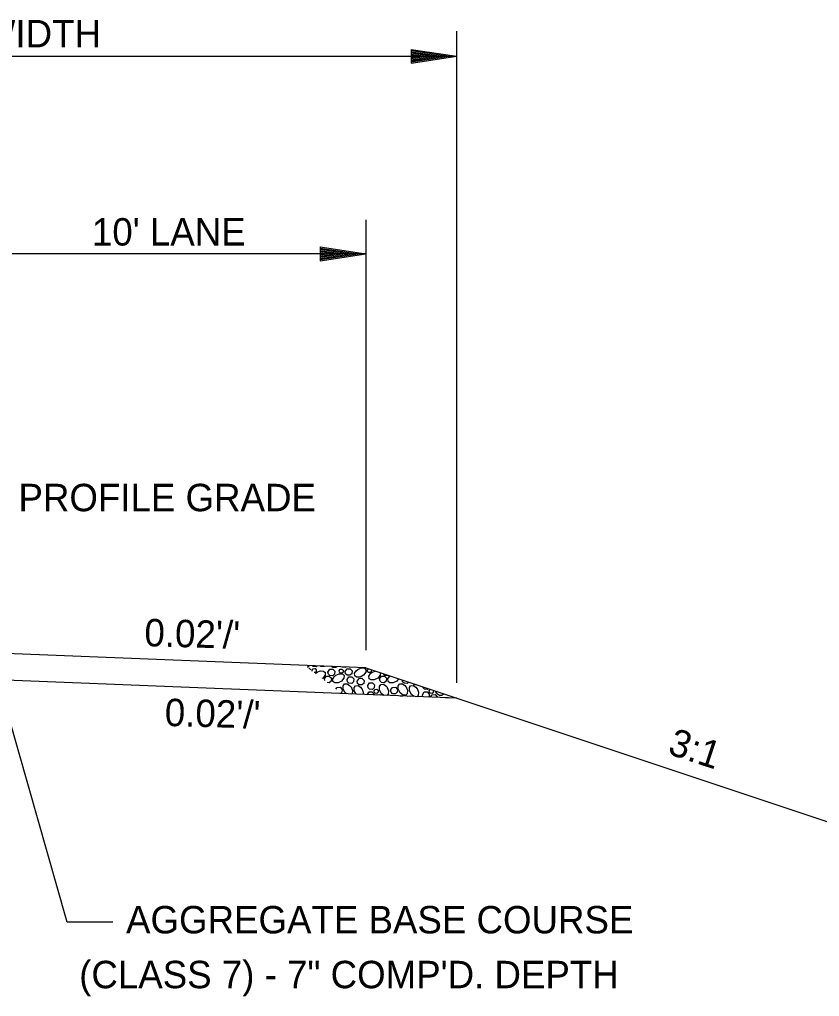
# Model space of a CAD drawing. Extents: x 2478 to 3210, y 439 to 841.
# Drawn here: x 3033.23 to 3068.23, y 483.63 to 526.4 of the extents above; entities that cross this region are included whole.
import ezdxf

# ---------------------------------------------------------------- set-up
doc = ezdxf.new("R2010")
doc.units = 0
doc.layers.add('R_Annotation', color=7, linetype='Continuous')
doc.layers.add('R_Dimension', color=7, linetype='Continuous')

msp = doc.modelspace()

# ---------------------------------------------------------------- linework, layer by layer
at = {"layer": 'R_Annotation'}
for p, q in [((3048.387, 498.012), (3028.387, 498.812)), ((3048.387, 498.012), (3074.678, 489.248)), ((3052.368, 496.685), (3028.34, 497.646))]:
    msp.add_line(p, q, dxfattribs=at)
at = {"layer": 'R_Dimension'}
for p, q in [((3052.368, 497.369), (3052.368, 525.892)), ((3004.405, 524.789), (3052.368, 524.789)), ((3050.368, 525.089), (3052.368, 524.789)), ((3050.368, 525.089), (3050.368, 524.489)), ((3050.368, 525.039), (3052.034, 524.789)), ((3050.368, 524.988), (3051.69, 524.789)), ((3050.368, 524.938), (3051.357, 524.789)), ((3050.368, 524.886), (3051.018, 524.789)), ((3050.368, 524.836), (3050.684, 524.789)), ((3050.368, 524.489), (3052.368, 524.789)), ((3050.368, 524.691), (3051.018, 524.789)), ((3050.368, 524.59), (3051.69, 524.789)), ((3050.368, 524.539), (3052.034, 524.789)), ((3050.368, 524.64), (3051.357, 524.789)), ((3050.368, 524.742), (3050.684, 524.789)), ((3048.387, 517.637), (3048.387, 498.798)), ((3046.386, 516.441), (3048.386, 516.141)), ((3046.386, 516.441), (3046.386, 515.841)), ((3046.386, 516.391), (3048.052, 516.141)), ((3046.386, 516.34), (3047.708, 516.141)), ((3046.386, 516.29), (3047.375, 516.141)), ((3046.386, 516.238), (3047.036, 516.141)), ((3046.386, 516.188), (3046.702, 516.141)), ((3048.387, 516.141), (3008.387, 516.141)), ((3046.386, 515.841), (3048.386, 516.141)), ((3046.386, 516.043), (3047.036, 516.141)), ((3046.386, 515.942), (3047.708, 516.141)), ((3046.386, 515.891), (3048.052, 516.141)), ((3046.386, 515.992), (3047.375, 516.141)), ((3046.386, 516.094), (3046.702, 516.141)), ((3046.038, 497.878), (3046.032, 497.917)), ((3046.174, 497.773), (3046.247, 497.827)), ((3048.447, 497.917), (3048.492, 497.977)), ((3048.652, 497.822), (3048.793, 497.877)), ((3046.581, 497.459), (3046.567, 497.532)), ((3051.157, 497.007), (3051.2, 497.074)), ((3048.442, 496.842), (3048.442, 496.842)), ((3050.871, 496.745), (3050.857, 496.842)), ((3052.217, 496.691), (3052.241, 496.727))]:
    msp.add_line(p, q, dxfattribs=at)
for points in [[(3045.897, 498.112), (3045.842, 498.052), (3045.812, 498.052)], [(3045.88, 497.999), (3045.902, 497.997), (3045.972, 497.932), (3045.972, 497.929)], [(3046.032, 497.917), (3046.082, 497.982), (3046.157, 497.987), (3046.212, 497.932), (3046.202, 497.857), (3046.157, 497.812), (3046.12, 497.815)], [(3046.235, 498.098), (3046.202, 498.067), (3046.077, 498.077), (3046.043, 498.106)], [(3046.237, 497.822), (3046.392, 497.882), (3046.532, 497.872), (3046.597, 497.812), (3046.597, 497.697), (3046.492, 497.572), (3046.457, 497.555)], [(3046.567, 498.085), (3046.562, 498.082), (3046.412, 498.077), (3046.392, 498.092)], [(3046.717, 497.832), (3046.807, 497.957), (3046.932, 497.962), (3047.022, 497.867), (3047.007, 497.742), (3046.932, 497.672), (3046.802, 497.682), (3046.747, 497.742), (3046.717, 497.832)], [(3047.105, 498.063), (3047.067, 498.027), (3046.937, 498.032), (3046.9, 498.072)], [(3047.212, 497.882), (3047.262, 497.957), (3047.337, 497.962), (3047.397, 497.902), (3047.387, 497.822), (3047.337, 497.782), (3047.262, 497.797), (3047.227, 497.822), (3047.212, 497.882)], [(3047.499, 498.048), (3047.482, 498.032), (3047.357, 498.042), (3047.345, 498.054)], [(3047.482, 497.857), (3047.557, 497.977), (3047.692, 497.982), (3047.787, 497.882), (3047.772, 497.757), (3047.687, 497.692), (3047.557, 497.697), (3047.497, 497.757), (3047.482, 497.857)], [(3048.027, 497.952), (3048.177, 498.012), (3048.317, 497.997), (3048.387, 497.932), (3048.387, 497.822), (3048.282, 497.692), (3048.132, 497.612), (3047.977, 497.612), (3047.902, 497.672), (3047.887, 497.782), (3047.962, 497.887), (3048.032, 497.952)], [(3048.627, 497.932), (3048.627, 497.932), (3048.617, 497.857), (3048.572, 497.812), (3048.497, 497.817), (3048.457, 497.857), (3048.447, 497.917)], [(3049.012, 497.804), (3049.012, 497.697), (3048.907, 497.572), (3048.752, 497.492), (3048.612, 497.487), (3048.522, 497.542), (3048.517, 497.657), (3048.582, 497.767), (3048.662, 497.827)], [(3037.308, 486.886), (3035.308, 486.886), (3032.304, 497.405)], [(3046.567, 497.532), (3046.652, 497.647), (3046.777, 497.652), (3046.872, 497.562), (3046.857, 497.432), (3046.772, 497.367), (3046.693, 497.373)], [(3047.067, 497.702), (3047.217, 497.762), (3047.362, 497.752), (3047.427, 497.687), (3047.422, 497.572), (3047.317, 497.442), (3047.167, 497.367), (3047.017, 497.367), (3046.937, 497.422), (3046.932, 497.537), (3046.997, 497.642), (3047.072, 497.702)], [(3047.557, 497.512), (3047.637, 497.627), (3047.767, 497.632), (3047.857, 497.537), (3047.847, 497.407), (3047.767, 497.337), (3047.637, 497.352), (3047.577, 497.412), (3047.557, 497.512)], [(3047.997, 497.437), (3048.087, 497.557), (3048.212, 497.562), (3048.302, 497.467), (3048.292, 497.337), (3048.212, 497.272), (3048.082, 497.277), (3048.022, 497.337), (3047.997, 497.437)], [(3048.462, 497.247), (3048.537, 497.357), (3048.677, 497.367), (3048.762, 497.272), (3048.752, 497.142), (3048.667, 497.077), (3048.537, 497.087), (3048.477, 497.142), (3048.462, 497.247)], [(3048.982, 497.532), (3049.067, 497.647), (3049.192, 497.652), (3049.287, 497.562), (3049.272, 497.432), (3049.187, 497.367), (3049.062, 497.377), (3049.002, 497.432), (3048.982, 497.532)], [(3049.362, 497.687), (3049.347, 497.672), (3049.217, 497.682), (3049.162, 497.742), (3049.157, 497.755)], [(3049.809, 497.538), (3049.732, 497.442), (3049.582, 497.367), (3049.432, 497.367), (3049.352, 497.422), (3049.347, 497.537), (3049.412, 497.642), (3049.437, 497.662)], [(3050.245, 497.393), (3050.182, 497.337), (3050.052, 497.352), (3049.992, 497.412), (3049.978, 497.482)], [(3047.073, 497.08), (3047.127, 497.157), (3047.257, 497.167), (3047.352, 497.077), (3047.332, 496.947), (3047.291, 496.912)], [(3047.532, 496.878), (3047.472, 496.927), (3047.387, 497.082), (3047.387, 497.227), (3047.447, 497.312), (3047.567, 497.317), (3047.667, 497.252), (3047.732, 497.172)], [(3047.732, 497.182), (3047.792, 497.027), (3047.777, 496.887), (3047.76, 496.869)], [(3047.951, 496.862), (3047.872, 497.007), (3047.872, 497.152), (3047.927, 497.232), (3048.042, 497.247), (3048.152, 497.172), (3048.212, 497.097)], [(3048.207, 497.107), (3048.267, 496.952), (3048.259, 496.849)], [(3048.442, 496.842), (3048.522, 496.962), (3048.647, 496.967), (3048.742, 496.867), (3048.739, 496.83)], [(3048.742, 497.007), (3048.787, 497.077), (3048.867, 497.082), (3048.922, 497.027), (3048.917, 496.947), (3048.867, 496.902), (3048.787, 496.912), (3048.752, 496.947), (3048.742, 497.007)], [(3049.179, 496.812), (3049.057, 496.902), (3048.982, 497.057), (3048.977, 497.207), (3049.042, 497.292), (3049.152, 497.297), (3049.262, 497.227), (3049.322, 497.152)], [(3049.312, 497.157), (3049.377, 497.007), (3049.362, 496.867), (3049.302, 496.808)], [(3049.462, 497.042), (3049.542, 497.157), (3049.672, 497.167), (3049.767, 497.077), (3049.747, 496.947), (3049.672, 496.882), (3049.542, 496.887), (3049.482, 496.947), (3049.462, 497.042)], [(3050.147, 497.182), (3050.207, 497.027), (3050.192, 496.887), (3050.127, 496.817), (3050.012, 496.827), (3049.887, 496.927), (3049.802, 497.082), (3049.802, 497.227), (3049.862, 497.312), (3049.982, 497.317), (3050.082, 497.252), (3050.147, 497.172)], [(3050.486, 496.76), (3050.372, 496.852), (3050.287, 497.007), (3050.287, 497.152), (3050.342, 497.232), (3050.457, 497.247), (3050.567, 497.172), (3050.627, 497.097)], [(3050.604, 497.273), (3050.497, 497.277), (3050.449, 497.325)], [(3050.622, 497.107), (3050.682, 496.952), (3050.672, 496.812), (3050.619, 496.755)], [(3050.857, 496.842), (3050.937, 496.962), (3051.062, 496.967), (3051.157, 496.867), (3051.147, 496.742), (3051.136, 496.734)], [(3051.115, 497.103), (3051.082, 497.077), (3050.952, 497.087), (3050.892, 497.142), (3050.886, 497.179)], [(3051.334, 497.03), (3051.337, 497.027), (3051.332, 496.947), (3051.282, 496.902), (3051.202, 496.912), (3051.167, 496.947), (3051.157, 497.007)], [(3051.778, 496.882), (3051.777, 496.867), (3051.712, 496.802), (3051.602, 496.807), (3051.472, 496.902), (3051.424, 496.999)], [(3048.851, 496.826), (3048.862, 496.842), (3048.997, 496.852), (3049.025, 496.819)], [(3049.901, 496.784), (3049.997, 496.787), (3050.005, 496.779)], [(3050.202, 496.772), (3050.207, 496.777), (3050.332, 496.787), (3050.353, 496.766)], [(3051.203, 496.732), (3051.277, 496.842), (3051.412, 496.852), (3051.497, 496.752), (3051.493, 496.72)], [(3051.871, 496.705), (3051.902, 496.717), (3052.037, 496.707), (3052.047, 496.698)]]:
    msp.add_lwpolyline(points, dxfattribs=at)

# ---------------------------------------------------------------- texts
at = {"layer": 'R_Annotation'}
for s, p in [('23\'-6" SUBGRADE WIDTH', (3017.547, 525.18)), ("10' LANE", (3036.394, 516.505)), ('PROFILE GRADE', (3033.179, 504.874)), ('AGGREGATE BASE COURSE', (3037.887, 486.394)), ('(CLASS 7) - 7" COMP\'D. DEPTH', (3035.836, 483.994))]:
    msp.add_text(s, height=1.2, dxfattribs=at).set_placement(p)
for s, rotation, p in [("0.02'/'", 358.3978, (3038.678, 498.969)), ("0.02'/'", 358.3978, (3039.569, 495.477)), ('3:1', 341.7155, (3061.545, 494.266))]:
    msp.add_text(s, height=1.2, rotation=rotation, dxfattribs=at).set_placement(p)

doc.saveas('drawing.dxf')
